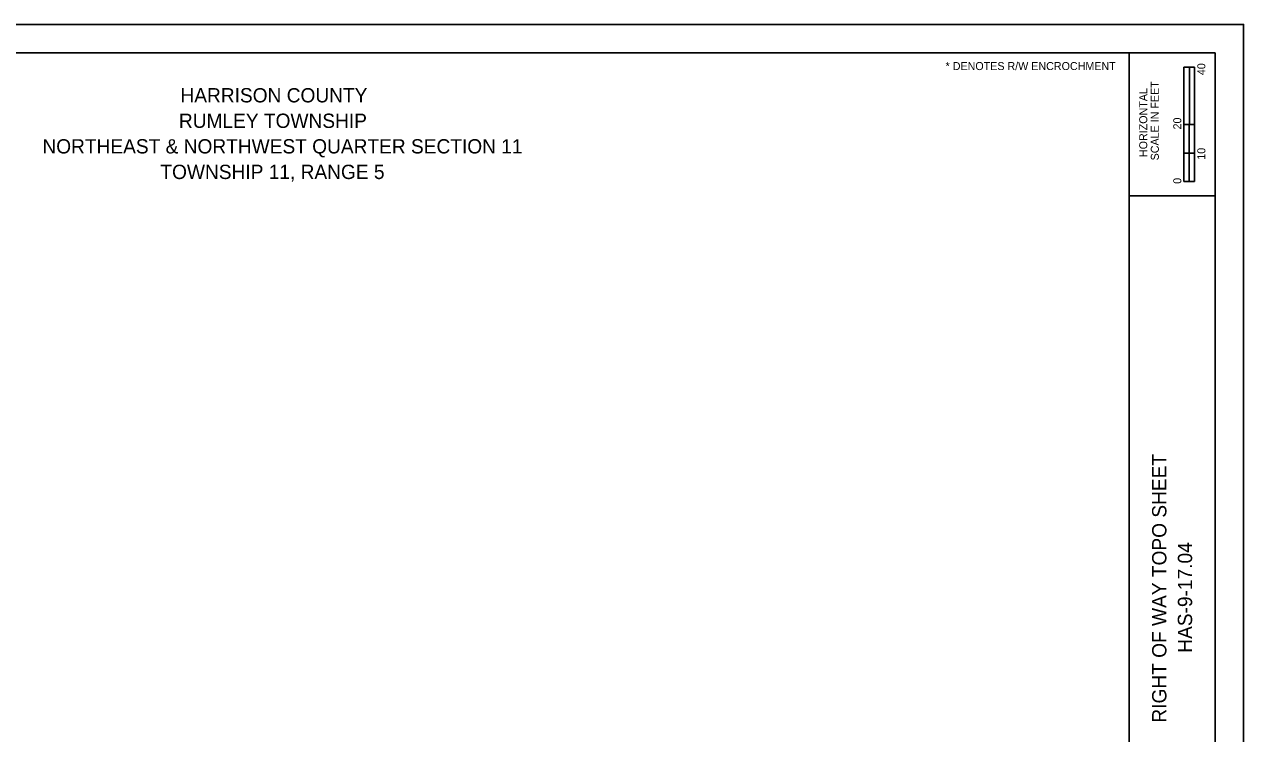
# Model space of a CAD drawing. Extents: x -0.2 to 34, y 0 to 22.
# Drawn here: x 12.68 to 34, y 9.59 to 22 of the extents above; entities that cross this region are included whole.
import ezdxf

# ---------------------------------------------------------------- set-up
doc = ezdxf.new("R2010")
doc.units = 0
for name, color, linetype in [('_CIVIL_CONSTRUCTION', 7, 'Continuous'), ('RW_X_CL', 7, 'Continuous'), ('RW_X_CL_100_Curve_Data', 7, 'Continuous'), ('RW_X_Esmt_SH', 7, 'Continuous')]:
    doc.layers.add(name, color=color, linetype=linetype)

msp = doc.modelspace()

# ---------------------------------------------------------------- linework, layer by layer
at = {"layer": '_CIVIL_CONSTRUCTION'}
msp.add_lwpolyline([(0, 0), (34, 0), (34, 22), (0, 22)], close=True, dxfattribs=at)
at = {"layer": 'RW_X_CL'}
for p, q in [((32, 0.5), (32, 21.5)), ((32, 19), (33.5, 19))]:
    msp.add_line(p, q, dxfattribs=at)
msp.add_lwpolyline([(1.5, 21.5), (33.5, 21.5), (33.5, 0.5), (1.5, 0.5)], close=True, dxfattribs=at)
at = {"layer": 'RW_X_Esmt_SH'}
for p, q in [((32.957, 19.25), (32.957, 21.25)), ((33.144, 21.25), (32.957, 21.25)), ((32.957, 20.25), (32.957, 21.25)), ((32.957, 21.25), (33.05, 21.25)), ((33.05, 21.25), (33.051, 21.25)), ((33.051, 21.25), (33.051, 20.25)), ((33.144, 21.25), (33.144, 19.25)), ((33.051, 20.25), (32.957, 20.25)), ((33.143, 20.25), (33.05, 20.25)), ((33.05, 20.25), (33.05, 19.75)), ((33.143, 19.75), (33.143, 20.25)), ((33.05, 19.75), (32.957, 19.75)), ((32.957, 19.75), (32.957, 19.25)), ((33.05, 19.25), (33.05, 19.75)), ((33.05, 19.75), (33.143, 19.75)), ((33.144, 19.25), (32.957, 19.25)), ((32.957, 19.25), (33.05, 19.25))]:
    msp.add_line(p, q, dxfattribs=at)

# ---------------------------------------------------------------- texts
at = {"layer": 'RW_X_CL_100_Curve_Data'}
msp.add_text('* DENOTES R/W ENCROCHMENT', height=0.14, dxfattribs=at).set_placement((28.789, 21.201))
at = {"layer": 'RW_X_Esmt_SH'}
for s, height, p in [('40', 0.14, (33.33, 21.112)), ('SCALE IN FEET', 0.14, (32.517, 19.621)), ('HORIZONTAL', 0.14, (32.315, 19.679)), ('20', 0.14, (32.91, 20.162)), ('10', 0.14, (33.33, 19.633)), ('0', 0.14, (32.91, 19.211)), ('RIGHT OF WAY TOPO SHEET', 0.25, (32.65, 9.787)), ('HAS-9-17.04', 0.25, (33.1, 11.009))]:
    msp.add_text(s, height=height, rotation=90, dxfattribs=at).set_placement(p)
for s, p in [('HARRISON COUNTY', (15.409, 20.635)), ('RUMLEY TOWNSHIP', (15.382, 20.189)), ('NORTHEAST & NORTHWEST QUARTER SECTION 11', (12.995, 19.742)), ('TOWNSHIP 11, RANGE 5', (15.058, 19.295))]:
    msp.add_text(s, height=0.25, dxfattribs=at).set_placement(p)

doc.saveas('drawing.dxf')
